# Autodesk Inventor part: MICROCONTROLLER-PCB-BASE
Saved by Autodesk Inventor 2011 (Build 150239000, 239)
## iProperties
Created: 2010-06
Part Number: MICROCONTROLLER-PCB-BASE
Document SubType Name: Modeling
Designer: kurdi
Density: 1 g/cm^3
Author: kurdi
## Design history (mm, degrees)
feature "Base1"
feature "Base2"
feature "Base3"
feature "Base4"
feature "Base5"
feature "Base6"
feature "Base7"
node "NONE"
node "NONE_1"
node "NONE_2"
node "NONE_3"
node "NONE_4"
node "NONE_5"
node "NONE_6"
